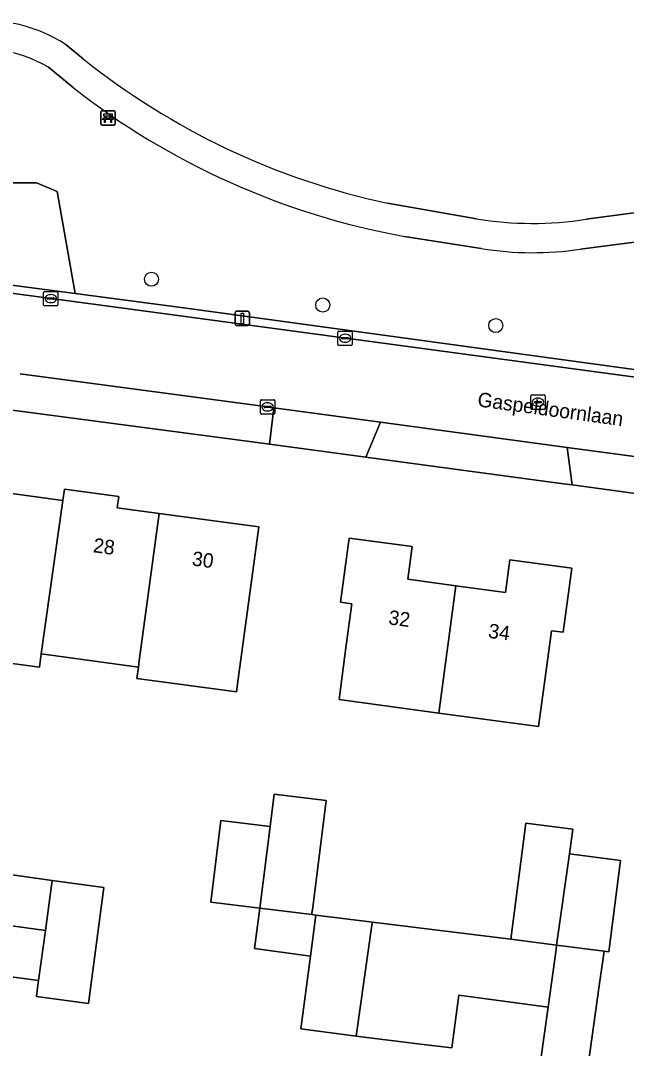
# Model space of a CAD drawing. Extents: x 161692 to 162379, y 380760 to 381678.
# Drawn here: x 162049 to 162091.1, y 380835.9 to 380907.3 of the extents above; entities that cross this region are included whole.
import ezdxf

# ---------------------------------------------------------------- set-up
doc = ezdxf.new("R2010")
doc.units = 0
for name, color, linetype in [('IMGEO_Bank', 7, 'Continuous'), ('IMGEO_Boom', 7, 'Continuous'), ('IMGEO_Erf', 7, 'Continuous'), ('IMGEO_Groenvoorziening', 7, 'Continuous'), ('IMGEO_Kolk', 7, 'Continuous'), ('IMGEO_Lichtmast', 7, 'Continuous'), ('IMGEO_Openbare_ruimte_label', 7, 'Continuous'), ('IMGEO_Pand', 7, 'Continuous'), ('IMGEO_Pand_nummerreeks', 7, 'Continuous'), ('IMGEO_Rijbaan_lokaal_open', 7, 'Continuous'), ('IMGEO_Rioolput', 7, 'Continuous'), ('IMGEO_Voetpad_gesloten', 7, 'Continuous'), ('IMGEO_Voetpad_open', 7, 'Continuous')]:
    doc.layers.add(name, color=color, linetype=linetype)

msp = doc.modelspace()

# ---------------------------------------------------------------- linework, layer by layer
at = {"layer": 'IMGEO_Bank'}
for p, q in [((162054.587, 380900.121), (162054.587, 380900.962)), ((162054.587, 380900.962), (162054.587, 380900.121)), ((162054.662, 380901.046), (162055.503, 380901.046)), ((162055.503, 380901.046), (162054.662, 380901.046)), ((162054.896, 380900.552), (162054.896, 380900.658)), ((162054.94, 380900.658), (162054.94, 380900.552)), ((162055.228, 380900.664), (162054.946, 380900.664)), ((162054.946, 380900.546), (162055.228, 380900.546)), ((162055.234, 380900.552), (162055.234, 380900.658)), ((162055.278, 380900.658), (162055.278, 380900.552)), ((162055.587, 380900.971), (162055.587, 380900.13)), ((162055.587, 380900.13), (162055.587, 380900.971)), ((162055.512, 380900.046), (162054.671, 380900.046)), ((162054.671, 380900.046), (162055.512, 380900.046)), ((162055.284, 380900.444), (162054.891, 380900.444))]:
    msp.add_line(p, q, dxfattribs=at)
for points in [[(162054.834, 380900.444), (162054.692, 380900.444), (162054.804, 380900.546), (162054.89, 380900.546)], [(162054.89, 380900.664), (162054.804, 380900.664), (162054.804, 380900.825), (162055.367, 380900.825), (162055.367, 380900.664), (162055.284, 380900.664)], [(162055.284, 380900.546), (162055.367, 380900.546), (162055.479, 380900.444), (162055.34, 380900.444)], [(162054.884, 380900.437), (162054.884, 380900.23), (162054.841, 380900.23), (162054.841, 380900.437)], [(162055.334, 380900.437), (162055.334, 380900.23), (162055.29, 380900.23), (162055.29, 380900.437)]]:
    msp.add_lwpolyline(points, dxfattribs=at)
for centre, radius, start, end in [((162054.665, 380900.968), 0.0779, 92.4484, 184.28452), ((162054.665, 380900.968), 0.0779, 92.4484, 184.28452), ((162054.889, 380900.657), 0.00671, 2.89567, 87.10433), ((162054.889, 380900.553), 0.00671, 272.89567, 357.10433), ((162054.946, 380900.657), 0.00671, 92.89567, 177.10433), ((162054.946, 380900.553), 0.00671, 182.89567, 267.10433), ((162055.228, 380900.657), 0.00671, 2.89567, 87.10433), ((162055.228, 380900.553), 0.00671, 272.89567, 357.10433), ((162055.285, 380900.657), 0.00671, 92.89567, 177.10433), ((162055.285, 380900.553), 0.00671, 182.89567, 267.10433), ((162055.509, 380900.968), 0.0779, 2.4484, 94.28452), ((162055.509, 380900.968), 0.0779, 2.4484, 94.28452), ((162054.665, 380900.124), 0.0779, 182.4484, 274.28452), ((162054.665, 380900.124), 0.0779, 182.4484, 274.28452), ((162054.834, 380900.437), 0.00671, 2.89567, 87.10433), ((162054.891, 380900.437), 0.00671, 92.89567, 177.10433), ((162055.283, 380900.437), 0.00671, 2.89567, 87.10433), ((162055.34, 380900.437), 0.00671, 92.89567, 177.10433), ((162055.509, 380900.124), 0.0779, 272.4484, 4.28452), ((162055.509, 380900.124), 0.0779, 272.4484, 4.28452)]:
    msp.add_arc(centre, radius, start, end, dxfattribs=at)
at = {"layer": 'IMGEO_Boom'}
for centre in [(162058.109, 380889.337), (162070.002, 380887.548), (162082.026, 380886.121)]:
    msp.add_circle(centre, 0.489, dxfattribs=at)
at = {"layer": 'IMGEO_Erf'}
for points in [[(162160.671, 380850.541), (162162.074, 380861.396), (162158.831, 380865.336), (162152.746, 380866.172), (162136.812, 380868.339), (162135.902, 380868.463), (162130.186, 380869.241), (162115.336, 380871.262), (162115.097, 380871.294), (162109.365, 380872.07), (162093.416, 380874.228), (162087.325, 380875.053), (162086.739, 380875.132), (162073.007, 380876.986), (162066.314, 380877.889), (162065.805, 380877.958), (162044.913, 380880.698), (162044.281, 380880.777)], [(162084.653, 380831.554), (162085.655, 380838.78), (162079.465, 380839.616), (162078.969, 380835.94), (162076.789, 380836.206), (162072.333, 380836.752), (162068.487, 380837.258), (162069.154, 380842.327), (162065.263, 380842.839), (162065.633, 380845.651), (162062.232, 380846.073), (162062.935, 380851.741), (162066.347, 380851.317), (162066.631, 380853.566), (162070.236, 380853.118), (162069.29, 380845.5), (162069.274, 380845.501), (162069.245, 380845.202), (162069.528, 380845.167), (162073.451, 380844.681), (162083.072, 380843.49), (162084.104, 380851.55), (162087.367, 380851.132), (162087.147, 380849.415), (162090.691, 380848.961), (162089.879, 380842.618), (162089.543, 380842.661), (162089.497, 380842.329), (162089.211, 380840.266), (162087.94, 380831.099)]]:
    msp.add_lwpolyline(points, dxfattribs=at)
for points in [[(162064.02, 380860.684), (162057.092, 380861.615), (162057.198, 380862.403), (162050.455, 380863.309), (162050.331, 380862.392), (162039.953, 380863.788), (162040.762, 380869.784), (162044.243, 380869.315), (162044.428, 380870.633), (162043.794, 380870.718), (162044.196, 380873.701), (162044.798, 380873.62), (162044.971, 380874.909), (162051.959, 380873.969), (162052.066, 380874.763), (162055.832, 380874.256), (162055.725, 380873.462), (162058.634, 380873.071), (162065.561, 380872.139), (162064.895, 380867.184), (162064.184, 380861.899)], [(162078.065, 380859.204), (162071.134, 380860.136), (162071.642, 380863.91), (162072.029, 380866.789), (162071.236, 380866.896), (162071.836, 380871.358), (162076.216, 380870.768), (162075.911, 380868.497), (162079.255, 380868.047), (162082.688, 380867.585), (162082.994, 380869.855), (162087.306, 380869.274), (162086.705, 380864.815), (162085.892, 380864.925), (162085.52, 380862.159), (162084.997, 380858.271)], [(162053.724, 380839.019), (162050.119, 380839.504), (162050.201, 380840.114), (162050.27, 380840.627), (162040.395, 380841.955), (162040.865, 380845.455), (162041.336, 380848.955), (162051.208, 380847.577), (162054.808, 380847.075)]]:
    msp.add_lwpolyline(points, close=True, dxfattribs=at)
at = {"layer": 'IMGEO_Groenvoorziening'}
for points in [[(162052.187, 380905.62), (162053.358, 380904.654)], [(162052.662, 380902.652), (162050.965, 380904.073)], [(162045.828, 380901.384), (162046.149, 380896.045), (162050.11, 380896.045), (162051.551, 380895.444), (162052.807, 380888.348), (162060.512, 380887.33), (162092.654, 380882.935), (162119.354, 380879.284), (162124.228, 380878.67), (162124.242, 380878.904), (162124.64, 380882.344), (162124.67, 380882.601)], [(162088.314, 380893.507), (162101.599, 380895.276)], [(162074.513, 380894.619), (162080.674, 380893.536)], [(162123.059, 380884.375), (162101.969, 380893.255), (162087.912, 380891.433)], [(162081.018, 380891.474), (162075.687, 380892.318)]]:
    msp.add_lwpolyline(points, dxfattribs=at)
msp.add_lwpolyline([(162052.807, 380888.348), (162051.551, 380895.444), (162050.11, 380896.045), (162046.149, 380896.045), (162045.828, 380901.384), (162029.978, 380897.87), (162031.098, 380891.221), (162037.112, 380890.421)], close=True, dxfattribs=at)
for centre, radius, start, end in [((162046.517, 380896.949), 10.36, 56.8163, 102.00364), ((162046.19, 380895.713), 9.628, 60.26505, 107.403), ((162085.21, 380944.487), 51.002, 231.35221, 257.89259), ((162084.985, 380943.852), 52.366, 231.88476, 259.77258), ((162084.585, 380917.49), 24.271, 260.7271, 278.83794), ((162084.596, 380913.445), 22.261, 260.75119, 278.56732)]:
    msp.add_arc(centre, radius, start, end, dxfattribs=at)
at = {"layer": 'IMGEO_Kolk'}
for p, q in [((162050.612, 380887.571), (162050.612, 380888.423)), ((162050.687, 380888.497), (162051.539, 380888.497)), ((162051.613, 380888.423), (162051.613, 380887.571)), ((162050.871, 380887.991), (162050.871, 380888.003)), ((162051.309, 380887.954), (162050.911, 380887.954)), ((162050.914, 380888.04), (162051.312, 380888.04)), ((162051.123, 380887.717), (162051.098, 380887.717)), ((162051.1, 380888.277), (162051.125, 380888.277)), ((162051.355, 380888.003), (162051.355, 380887.991)), ((162051.539, 380887.497), (162050.687, 380887.497)), ((162071.053, 380884.813), (162071.053, 380885.665)), ((162071.128, 380885.739), (162071.98, 380885.739)), ((162072.054, 380885.665), (162072.054, 380884.813)), ((162071.312, 380885.233), (162071.312, 380885.245)), ((162071.75, 380885.196), (162071.352, 380885.196)), ((162071.355, 380885.282), (162071.753, 380885.282)), ((162071.564, 380884.959), (162071.539, 380884.959)), ((162071.541, 380885.519), (162071.566, 380885.519)), ((162071.796, 380885.245), (162071.796, 380885.233)), ((162071.98, 380884.739), (162071.128, 380884.739)), ((162065.675, 380880.047), (162065.675, 380880.899)), ((162065.75, 380880.973), (162066.602, 380880.973)), ((162066.163, 380880.753), (162066.188, 380880.753)), ((162066.676, 380880.899), (162066.676, 380880.047)), ((162066.602, 380879.973), (162065.75, 380879.973)), ((162065.934, 380880.467), (162065.934, 380880.479)), ((162066.372, 380880.43), (162065.974, 380880.43)), ((162065.977, 380880.516), (162066.375, 380880.516)), ((162066.186, 380880.193), (162066.161, 380880.193)), ((162066.418, 380880.479), (162066.418, 380880.467))]:
    msp.add_line(p, q, dxfattribs=at)
for points in [[(162050.612, 380887.571), (162050.612, 380888.423)], [(162050.687, 380888.497), (162051.539, 380888.497)], [(162051.613, 380888.423), (162051.613, 380887.571)], [(162051.539, 380887.497), (162050.687, 380887.497)], [(162071.053, 380884.813), (162071.053, 380885.665)], [(162071.128, 380885.739), (162071.98, 380885.739)], [(162072.054, 380885.665), (162072.054, 380884.813)], [(162071.98, 380884.739), (162071.128, 380884.739)], [(162065.675, 380880.047), (162065.675, 380880.899)], [(162065.75, 380880.973), (162066.602, 380880.973)], [(162066.676, 380880.899), (162066.676, 380880.047)], [(162066.602, 380879.973), (162065.75, 380879.973)]]:
    msp.add_lwpolyline(points, dxfattribs=at)
for centre, radius, start, end in [((162050.689, 380888.421), 0.0765, 91.55205, 178.44795), ((162050.689, 380888.421), 0.0765, 91.55205, 178.44795), ((162051.537, 380888.421), 0.0765, 1.55205, 88.44795), ((162051.537, 380888.421), 0.0765, 1.55205, 88.44795), ((162050.911, 380888), 0.0403, 85.87752, 175.75265), ((162050.908, 380887.99), 0.0366, 178.93798, 274.71019), ((162051.312, 380887.997), 0.043, 264.86636, 352.45326), ((162051.316, 380888.002), 0.0386, 1.73085, 96.63898), ((162050.689, 380887.573), 0.0765, 181.55205, 268.44795), ((162050.689, 380887.573), 0.0765, 181.55205, 268.44795), ((162051.537, 380887.573), 0.0765, 271.55205, 358.44795), ((162051.537, 380887.573), 0.0765, 271.55205, 358.44795), ((162071.13, 380885.663), 0.0765, 91.55205, 178.44795), ((162071.13, 380885.663), 0.0765, 91.55205, 178.44795), ((162071.978, 380885.663), 0.0765, 1.55205, 88.44795), ((162071.978, 380885.663), 0.0765, 1.55205, 88.44795), ((162071.13, 380884.815), 0.0765, 181.55205, 268.44795), ((162071.13, 380884.815), 0.0765, 181.55205, 268.44795), ((162071.352, 380885.242), 0.0403, 85.87752, 175.75265), ((162071.349, 380885.232), 0.0366, 178.93798, 274.71019), ((162071.753, 380885.239), 0.043, 264.86636, 352.45326), ((162071.757, 380885.244), 0.0386, 1.73085, 96.63898), ((162071.978, 380884.815), 0.0765, 271.55205, 358.44795), ((162071.978, 380884.815), 0.0765, 271.55205, 358.44795), ((162065.752, 380880.897), 0.0765, 91.55205, 178.44795), ((162065.752, 380880.897), 0.0765, 91.55205, 178.44795), ((162066.6, 380880.897), 0.0765, 1.55205, 88.44795), ((162066.6, 380880.897), 0.0765, 1.55205, 88.44795), ((162065.752, 380880.049), 0.0765, 181.55205, 268.44795), ((162065.752, 380880.049), 0.0765, 181.55205, 268.44795), ((162065.974, 380880.476), 0.0403, 85.87752, 175.75265), ((162065.971, 380880.466), 0.0366, 178.93798, 274.71019), ((162066.375, 380880.473), 0.043, 264.86636, 352.45326), ((162066.379, 380880.478), 0.0386, 1.73085, 96.63898), ((162066.6, 380880.049), 0.0765, 271.55205, 358.44795), ((162066.6, 380880.049), 0.0765, 271.55205, 358.44795)]:
    msp.add_arc(centre, radius, start, end, dxfattribs=at)
for centre, major_axis, ratio, start_param, end_param in [((162051.099, 380887.997), (-0.387, 0.002), 0.722429, 4.712389, 7.853982), ((162051.124, 380887.997), (-0.39, 0.002), 0.717154, 1.570796, 4.712389), ((162071.54, 380885.239), (-0.387, 0.002), 0.722429, 4.712389, 7.853982), ((162071.565, 380885.239), (-0.39, 0.002), 0.717154, 1.570796, 4.712389), ((162066.162, 380880.473), (-0.387, 0.002), 0.722429, 4.712389, 7.853982), ((162066.187, 380880.473), (-0.39, 0.002), 0.717154, 1.570796, 4.712389)]:
    msp.add_ellipse(centre, major_axis=major_axis, ratio=ratio, start_param=start_param, end_param=end_param, dxfattribs=at)
at = {"layer": 'IMGEO_Lichtmast'}
for p, q in [((162063.921, 380886.215), (162063.921, 380887.015)), ((162063.921, 380887.015), (162063.921, 380886.215)), ((162064.021, 380887.115), (162064.811, 380887.115)), ((162064.811, 380887.115), (162064.021, 380887.115)), ((162064.911, 380887.015), (162064.911, 380886.215)), ((162064.911, 380886.215), (162064.911, 380887.015)), ((162064.811, 380886.115), (162064.021, 380886.115)), ((162064.021, 380886.115), (162064.811, 380886.115))]:
    msp.add_line(p, q, dxfattribs=at)
msp.add_lwpolyline([(162064.341, 380886.99), (162064.491, 380886.99), (162064.491, 380886.24), (162064.341, 380886.24), (162064.341, 380886.99)], dxfattribs=at)
for centre, start, end in [((162064.021, 380887.015), 90, 180), ((162064.021, 380887.015), 90, 180), ((162064.811, 380887.015), 0, 90), ((162064.811, 380887.015), 360, 90), ((162064.021, 380886.215), 180, 270), ((162064.021, 380886.215), 180, 270), ((162064.811, 380886.215), 270, 0), ((162064.811, 380886.215), 270, 0)]:
    msp.add_arc(centre, 0.1, start, end, dxfattribs=at)
at = {"layer": 'IMGEO_Pand'}
for points in [[(162051.959, 380873.969), (162044.971, 380874.909), (162044.798, 380873.62), (162044.196, 380873.701), (162043.794, 380870.718), (162044.428, 380870.633), (162044.243, 380869.315), (162040.762, 380869.784), (162039.953, 380863.788), (162050.331, 380862.392), (162050.455, 380863.309)], [(162051.959, 380873.969), (162050.455, 380863.309), (162057.198, 380862.403), (162057.256, 380862.831), (162058.634, 380873.071), (162055.725, 380873.462), (162055.832, 380874.256), (162052.066, 380874.763)], [(162065.561, 380872.139), (162058.634, 380873.071), (162057.256, 380862.831), (162057.198, 380862.403), (162057.092, 380861.615), (162064.02, 380860.684), (162064.184, 380861.899), (162064.895, 380867.184)], [(162078.065, 380859.204), (162079.255, 380868.047), (162075.911, 380868.497), (162076.216, 380870.768), (162071.836, 380871.358), (162071.236, 380866.896), (162072.029, 380866.789), (162071.642, 380863.91), (162071.134, 380860.136)], [(162078.065, 380859.204), (162084.997, 380858.271), (162085.52, 380862.159), (162085.892, 380864.925), (162086.705, 380864.815), (162087.306, 380869.274), (162082.994, 380869.855), (162082.688, 380867.585), (162079.255, 380868.047)], [(162070.236, 380853.118), (162066.631, 380853.566), (162066.347, 380851.317), (162065.633, 380845.651), (162069.245, 380845.202), (162069.274, 380845.501), (162069.29, 380845.5)], [(162066.347, 380851.317), (162062.935, 380851.741), (162062.232, 380846.073), (162065.633, 380845.651)], [(162087.147, 380849.415), (162087.367, 380851.132), (162084.104, 380851.55), (162083.072, 380843.49), (162086.251, 380843.082)], [(162090.691, 380848.961), (162087.147, 380849.415), (162086.251, 380843.082), (162089.543, 380842.661), (162089.879, 380842.618)], [(162051.208, 380847.577), (162041.336, 380848.955), (162040.865, 380845.455), (162050.738, 380844.092)], [(162051.208, 380847.577), (162050.738, 380844.092), (162050.27, 380840.627), (162050.201, 380840.114), (162050.119, 380839.504), (162053.724, 380839.019), (162054.808, 380847.075)], [(162069.528, 380845.167), (162069.245, 380845.202), (162065.633, 380845.651), (162065.263, 380842.839), (162069.154, 380842.327)], [(162050.27, 380840.627), (162050.738, 380844.092), (162040.865, 380845.455), (162040.395, 380841.955)], [(162073.421, 380844.468), (162073.451, 380844.681), (162069.528, 380845.167), (162069.154, 380842.327), (162068.487, 380837.258), (162072.333, 380836.752)], [(162079.465, 380839.616), (162085.655, 380838.78), (162086.21, 380842.785), (162086.251, 380843.082), (162083.072, 380843.49), (162073.451, 380844.681), (162073.421, 380844.468), (162072.333, 380836.752), (162076.789, 380836.206), (162078.969, 380835.94)], [(162089.211, 380840.266), (162089.497, 380842.329), (162089.543, 380842.661), (162086.251, 380843.082), (162086.21, 380842.785), (162085.655, 380838.78), (162084.653, 380831.554), (162087.94, 380831.099)]]:
    msp.add_lwpolyline(points, close=True, dxfattribs=at)
at = {"layer": 'IMGEO_Rijbaan_lokaal_open'}
msp.add_lwpolyline([(162048.989, 380882.779), (162066.177, 380880.475), (162066.61, 380880.416), (162074.022, 380879.413), (162086.972, 380877.66), (162093.903, 380876.722), (162109.31, 380874.634), (162115.858, 380873.747), (162130.159, 380871.815), (162137.142, 380870.872), (162138.17, 380870.733), (162150.394, 380869.088), (162158.496, 380867.964), (162162.848, 380867.367), (162169.904, 380866.398), (162170.61, 380871.806), (162163.55, 380872.779), (162154.919, 380873.969), (162091.896, 380882.503), (162058.39, 380887.022), (162030.224, 380890.812)], dxfattribs=at)
at = {"layer": 'IMGEO_Rioolput'}
for p, q in [((162084.529, 380881.3), (162085.381, 380881.3)), ((162084.454, 380880.374), (162084.454, 380881.226)), ((162084.713, 380880.794), (162084.713, 380880.806)), ((162085.151, 380880.757), (162084.753, 380880.757)), ((162084.756, 380880.843), (162085.154, 380880.843)), ((162084.942, 380881.08), (162084.967, 380881.08)), ((162085.197, 380880.806), (162085.197, 380880.794)), ((162085.455, 380881.226), (162085.455, 380880.374)), ((162085.381, 380880.3), (162084.529, 380880.3)), ((162084.965, 380880.52), (162084.94, 380880.52))]:
    msp.add_line(p, q, dxfattribs=at)
for points in [[(162084.529, 380881.3), (162085.381, 380881.3)], [(162084.454, 380880.374), (162084.454, 380881.226)], [(162085.455, 380881.226), (162085.455, 380880.374)], [(162085.381, 380880.3), (162084.529, 380880.3)]]:
    msp.add_lwpolyline(points, dxfattribs=at)
for centre, radius, start, end in [((162084.531, 380881.224), 0.0765, 91.55205, 178.44795), ((162084.531, 380881.224), 0.0765, 91.55205, 178.44795), ((162085.379, 380881.224), 0.0765, 1.55205, 88.44795), ((162085.379, 380881.224), 0.0765, 1.55205, 88.44795), ((162084.753, 380880.803), 0.0403, 85.87752, 175.75265), ((162084.75, 380880.793), 0.0366, 178.93798, 274.71019), ((162085.154, 380880.8), 0.043, 264.86636, 352.45326), ((162085.158, 380880.805), 0.0386, 1.73085, 96.63898), ((162084.531, 380880.376), 0.0765, 181.55205, 268.44795), ((162084.531, 380880.376), 0.0765, 181.55205, 268.44795), ((162085.379, 380880.376), 0.0765, 271.55205, 358.44795), ((162085.379, 380880.376), 0.0765, 271.55205, 358.44795)]:
    msp.add_arc(centre, radius, start, end, dxfattribs=at)
for centre, major_axis, ratio, start_param, end_param in [((162084.941, 380880.8), (-0.387, 0.002), 0.722429, 4.712389, 7.853982), ((162084.966, 380880.8), (-0.39, 0.002), 0.717154, 1.570796, 4.712389)]:
    msp.add_ellipse(centre, major_axis=major_axis, ratio=ratio, start_param=start_param, end_param=end_param, dxfattribs=at)
at = {"layer": 'IMGEO_Voetpad_gesloten'}
for points in [[(162053.358, 380904.654), (162052.187, 380905.62)], [(162050.965, 380904.073), (162052.662, 380902.652)], [(162101.599, 380895.276), (162088.314, 380893.507)], [(162080.674, 380893.536), (162074.513, 380894.619)], [(162087.912, 380891.433), (162101.969, 380893.255), (162123.059, 380884.375)], [(162075.687, 380892.318), (162081.018, 380891.474)]]:
    msp.add_lwpolyline(points, dxfattribs=at)
for centre, radius, start, end in [((162046.517, 380896.949), 10.36, 56.8163, 102.00364), ((162046.19, 380895.713), 9.628, 60.26505, 107.403), ((162085.21, 380944.487), 51.002, 231.35221, 257.89259), ((162084.985, 380943.852), 52.366, 231.88476, 259.77258), ((162084.585, 380917.49), 24.271, 260.7271, 278.83794), ((162084.596, 380913.445), 22.261, 260.75119, 278.56732)]:
    msp.add_arc(centre, radius, start, end, dxfattribs=at)
at = {"layer": 'IMGEO_Voetpad_open'}
for points in [[(162030.224, 380890.812), (162058.39, 380887.022), (162091.896, 380882.503), (162154.919, 380873.969), (162163.55, 380872.779), (162170.61, 380871.806), (162172.232, 380871.583), (162172.446, 380871.543), (162172.879, 380872.08), (162163.634, 380873.357), (162156.037, 380874.407), (162145.584, 380875.831), (162131.289, 380877.654), (162126.199, 380878.375), (162126.267, 380878.692), (162124.242, 380878.904), (162124.228, 380878.67), (162119.354, 380879.284), (162092.654, 380882.935), (162060.512, 380887.33), (162052.807, 380888.348), (162037.112, 380890.421)], [(162039.853, 380881.332), (162044.281, 380880.777), (162044.913, 380880.698), (162065.805, 380877.958), (162066.314, 380877.889), (162066.61, 380880.416), (162066.177, 380880.475), (162048.989, 380882.779)]]:
    msp.add_lwpolyline(points, dxfattribs=at)
for points in [[(162066.61, 380880.416), (162066.314, 380877.889), (162073.007, 380876.986), (162074.022, 380879.413)], [(162074.022, 380879.413), (162073.007, 380876.986), (162086.739, 380875.132), (162087.325, 380875.053), (162086.972, 380877.66)], [(162086.972, 380877.66), (162087.325, 380875.053), (162093.416, 380874.228), (162093.903, 380876.722)]]:
    msp.add_lwpolyline(points, close=True, dxfattribs=at)

# ---------------------------------------------------------------- texts
at = {"layer": 'IMGEO_Openbare_ruimte_label'}
msp.add_text('Gaspeldoornlaan', height=1, rotation=352.18582, dxfattribs=at).set_placement((162080.711, 380880.517))
at = {"layer": 'IMGEO_Pand_nummerreeks'}
for s, rotation, p in [('28', 352.33792, (162054.012, 380870.384)), ('30', 352.33955, (162060.876, 380869.461)), ('32', 352.33796, (162074.529, 380865.373)), ('34', 352.33796, (162081.464, 380864.44))]:
    msp.add_text(s, height=1, rotation=rotation, dxfattribs=at).set_placement(p)

doc.saveas('drawing.dxf')
